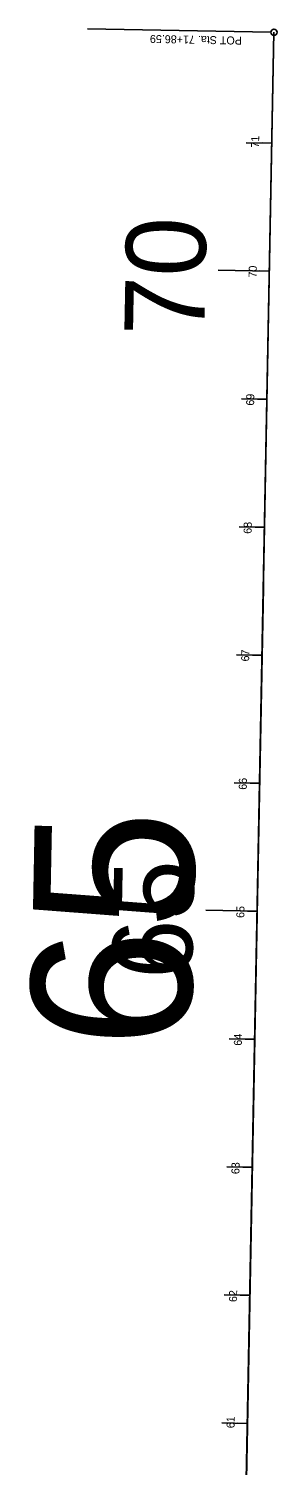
# Model space of a CAD drawing. Extents: x 1281433 to 1457183, y 526241 to 603611.
# Drawn here: x 1403696 to 1403890, y 577920 to 579042 of the extents above; entities that cross this region are included whole.
import ezdxf

# ---------------------------------------------------------------- set-up
doc = ezdxf.new("R2010")
doc.units = 0
for name, color, linetype in [('Level 20', 7, 'Continuous'), ('Level 21', 7, 'Continuous'), ('Level 22', 7, 'Continuous'), ('Level 4', 7, 'Continuous'), ('Level 6', 7, 'Continuous'), ('Level 7', 7, 'Continuous')]:
    doc.layers.add(name, color=color, linetype=linetype)

msp = doc.modelspace()

# ---------------------------------------------------------------- linework, layer by layer
at = {"layer": 'Level 20'}
msp.add_line((1403855.7, 577353.1), (1403887.9, 579039.4), dxfattribs=at)
at = {"layer": 'Level 21'}
msp.add_line((1403837.4, 576396.9), (1403887.9, 579039.4), dxfattribs=at)
msp.add_line((1403837.4, 576396.9), (1403887.9, 579039.4), dxfattribs=at)
msp.add_line((1403837.4, 576396.9), (1403887.9, 579039.4), dxfattribs=at)
at = {"layer": 'Level 22'}
msp.add_line((1403837.4, 576396.9), (1403879.6, 578605.5), dxfattribs=at)
at = {"layer": 'Level 4'}
for p, q in [((1403886.3, 578952.8), (1403866.3, 578953.2)), ((1403884.4, 578852.8), (1403844.4, 578853.6)), ((1403882.5, 578752.9), (1403862.5, 578753.2)), ((1403880.6, 578652.9), (1403860.6, 578653.3)), ((1403878.6, 578552.9), (1403858.6, 578553.3)), ((1403876.7, 578452.9), (1403856.7, 578453.3)), ((1403874.8, 578352.9), (1403834.8, 578353.7)), ((1403872.9, 578253), (1403852.9, 578253.3)), ((1403871, 578153), (1403851, 578153.4)), ((1403869.1, 578053), (1403849.1, 578053.4)), ((1403867.2, 577953), (1403847.2, 577953.4))]:
    msp.add_line(p, q, dxfattribs=at)
at = {"layer": 'Level 6'}
for p, q in [((1403885.4, 579039.4), (1403742.4, 579042.2)), ((1403886.3, 578952.8), (1403878.8, 578953)), ((1403884.4, 578852.8), (1403876.9, 578853)), ((1403882.5, 578752.9), (1403875, 578753)), ((1403880.6, 578652.9), (1403873.1, 578653)), ((1403878.6, 578552.9), (1403871.1, 578553)), ((1403876.7, 578452.9), (1403869.2, 578453.1)), ((1403874.8, 578352.9), (1403867.3, 578353.1)), ((1403872.9, 578253), (1403865.4, 578253.1)), ((1403871, 578153), (1403863.5, 578153.1)), ((1403869.1, 578053), (1403861.6, 578053.1)), ((1403867.2, 577953), (1403859.7, 577953.2))]:
    msp.add_line(p, q, dxfattribs=at)
msp.add_circle((1403887.9, 579039.4), 2.5, dxfattribs=at)
at = {"layer": 'Level 7'}
msp.add_line((1403874.8, 578352.9), (1403834.8, 578353.7), dxfattribs=at)

# ---------------------------------------------------------------- texts
at = {"layer": 'Level 4'}
for s, p in [('70', (1403833.4, 578801.7)), ('65', (1403823.8, 578299.6))]:
    msp.add_text(s, height=62.4, rotation=88.9037, dxfattribs=at).set_placement(p)
at = {"layer": 'Level 6'}
for s, rotation, p in [('POT Sta. 71+86.59', 178.9037, (1403862.9, 579036)), ('71', 88.9037, (1403876.2, 578949.2)), ('70', 88.9037, (1403874.3, 578847.8)), ('69', 88.9037, (1403872.4, 578747.8)), ('68', 88.9037, (1403870.4, 578647.7)), ('67', 88.9037, (1403868.5, 578548)), ('66', 88.9037, (1403866.6, 578447.8)), ('65', 88.9037, (1403864.7, 578347.7)), ('64', 88.9037, (1403862.8, 578247.9)), ('63', 88.9037, (1403860.9, 578147.6)), ('62', 88.9037, (1403859, 578047.7)), ('61', 88.9037, (1403857.1, 577949.2))]:
    msp.add_text(s, height=6.25, rotation=rotation, dxfattribs=at).set_placement(p)
at = {"layer": 'Level 7'}
msp.add_text('65', height=125, rotation=88.9037, dxfattribs=at).set_placement((1403822.7, 578245.2))

doc.saveas('drawing.dxf')
